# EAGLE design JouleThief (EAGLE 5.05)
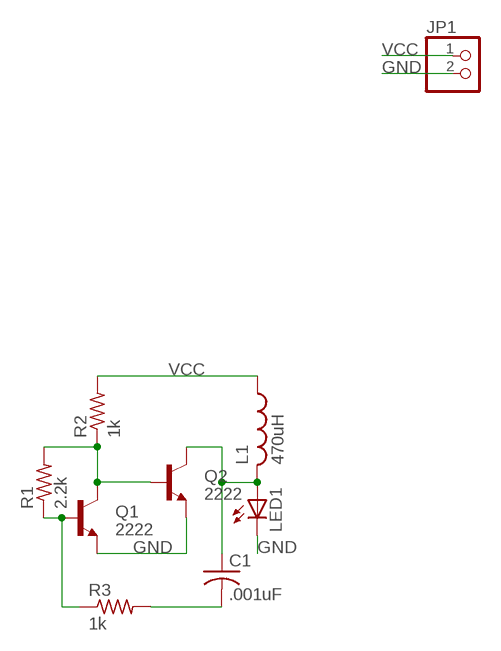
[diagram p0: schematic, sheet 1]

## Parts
C1  .001uF  C-US025-024X044  [C025-024X044]
JP1  PINHD-1X2  [1X02]
L1  470uH  L-US0204/7  [0204/7]
LED1  LED5MM  [LED5MM]
Q1  2222  TRANSISTOR_NPNTO92  [TO-92]
Q2  2222  TRANSISTOR_NPNTO92  [TO-92]
R1  2.2k  R-US_0204/2V  [0204V]
R2  1k  R-US_0204/2V  [0204V]
R3  1k  R-US_0204/2V  [0204V]

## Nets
GND: JP1.2 LED1.K(C) Q1.1(E) Q2.1(E)
N$1: C1.1 L1.2 LED1.A Q2.3(C)
N$2: Q1.2(B) R1.1 R3.1
N$3: Q1.3(C) Q2.2(B) R1.2 R2.1
N$4: C1.2 R3.2
VCC: JP1.1 L1.1 R2.2

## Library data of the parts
C1 = resistor:C-US: CAPACITOR, American symbol
JP1 = pinhead:PINHD-1X2: PIN HEADER
L1 = resistor:L-US: INDUCTOR, American symbol
LED1 = SparkFun:LED: LEDs
Q1 Q2 = SparkFun:TRANSISTOR_NPN: Transistor NPN BJT configuration in SOT23 package. MMBT2222 is the common NPN we use. Double check BCE configuration again layout.
R1-R3 = resistor:R-US_: RESISTOR, American symbol

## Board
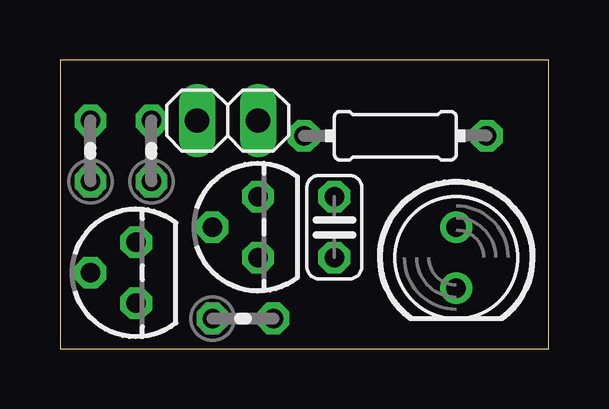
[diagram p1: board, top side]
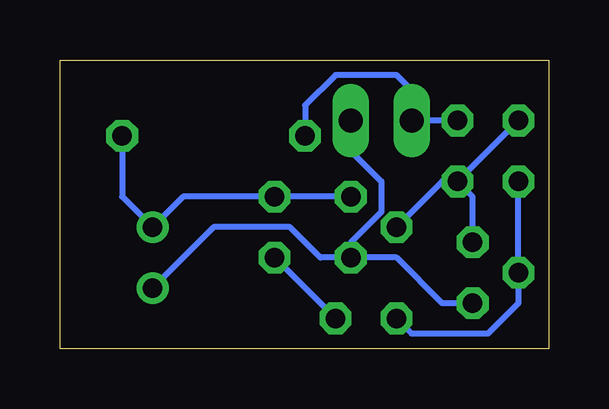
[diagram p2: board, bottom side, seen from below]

Size 20.37 x 12.05 mm. Coordinates in mm from the lower left corner, seen from the top.
Outline: 0,0 20.37,0 20.37,12.05 0,12.05 0,0
Copper layers (1*16): Top 0.035mm / dielectric 1.5mm / Bottom 0.035mm
Design rules "default": minimum track width 10mil, minimum drill 24mil, track to track 8mil, track to pad 8mil, pad to pad 8mil, via to via 8mil, smd to smd 8mil, copper to edge 40mil, drill to drill 8mil, minimum pad ring 10mil, minimum via ring 8mil, stop-mask expansion 4mil, vias tented up to drill 0mil, thermal gap 10mil

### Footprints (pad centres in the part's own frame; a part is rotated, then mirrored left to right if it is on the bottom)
C025-024X044 = drill 0.813 octagon: 1 -1.27,0; 2 1.27,0
1X02 = drill 1.016 long: 1 -1.27,0; 2 1.27,0
0204/7 = drill 0.813 octagon: 1 -3.81,0; 2 3.81,0
LED5MM = drill 0.813: A -1.27,0; K 1.27,0
TO-92 = drill 0.813 octagon: 1 -1.27,0; 2 0,1.905; 3 1.27,0
0204V = drill 0.813 octagon: 1 -1.27,0; 2 1.27,0

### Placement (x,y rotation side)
C1  11.43,5.08 270 top
JP1  6.99,9.53 0 top
L1  13.97,8.89 0 top
LED1  16.51,3.81 270 top
Q1  3.17,3.17 90 top
Q2  8.26,5.08 90 top
R1  1.27,8.26 90 top
R2  3.81,8.26 90 top
R3  7.62,1.27 0 top

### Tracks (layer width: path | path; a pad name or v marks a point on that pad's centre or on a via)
GND
  Bottom 0.254: Q1.1 4.45,1.91 6.35,3.81 Q2.1 | Q2.1 9.53,3.81 10.79,5.08 13.97,5.08 LED1.K | JP1.2 8.26,8.26 6.99,6.99 6.99,5.71 8.26,4.45 Q2.1
N$1
  Bottom 0.254: Q2.3 C1.1 15.24,6.35 LED1.A 17.78,6.35 L1.2
N$2
  Bottom 0.254: R3.1 5.71,0.64 2.54,0.64 1.27,1.91 Q1.2 R1.1
N$3
  Bottom 0.254: Q1.3 3.17,6.35 R2.1 | R1.2 R2.1 | R2.1 4.45,6.99 Q2.2
N$4
  Bottom 0.254: R3.2 C1.2
VCC
  Bottom 0.254: R2.2 JP1.1 5.71,10.79 6.35,11.43 8.89,11.43 10.16,10.16 L1.1

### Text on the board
tPlace: _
